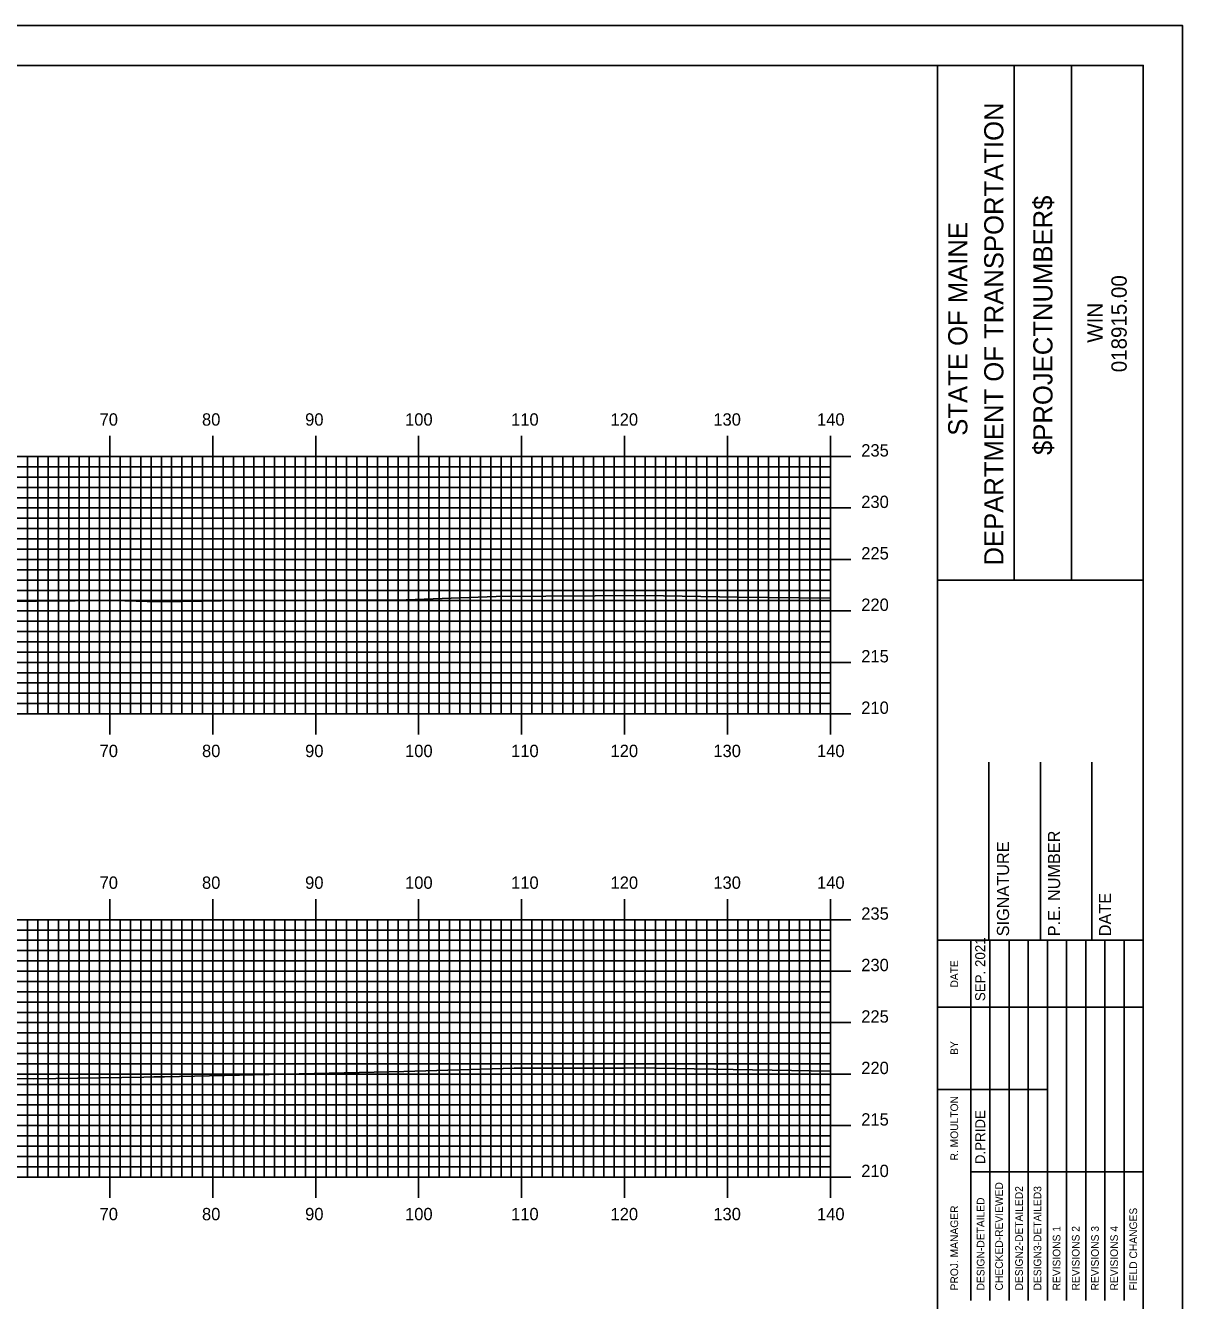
# Model space of a CAD drawing. Extents: x 1804290 to 1804634, y 442591 to 442811.
# Drawn here: x 1804518 to 1804630.4, y 442686.7 to 442810.5 of the extents above; entities that cross this region are included whole.
import ezdxf

# ---------------------------------------------------------------- set-up
doc = ezdxf.new("R2010")
doc.units = 0
for name, color, linetype in [('BORDER', 7, 'Continuous'), ('H_V ANNOTATION', 7, 'Continuous'), ('MAJOR', 7, 'Continuous'), ('MINOR', 7, 'Continuous'), ('PLOT BOUNDARY', 7, 'Continuous'), ('S_Roadway_Centerline', 7, 'Continuous')]:
    doc.layers.add(name, color=color, linetype=linetype)

msp = doc.modelspace()

# ---------------------------------------------------------------- linework, layer by layer
at = {"layer": 'BORDER'}
for p, q in [((1804606.57, 442596.67), (1804606.57, 442806.67)), ((1804614.02, 442756.66), (1804614.02, 442806.66)), ((1804619.61, 442756.66), (1804619.61, 442806.66)), ((1804606.57, 442756.65), (1804626.57, 442756.65)), ((1804611.57, 442721.67), (1804611.57, 442738.97)), ((1804616.57, 442721.67), (1804616.57, 442738.97)), ((1804621.57, 442721.67), (1804621.57, 442738.97)), ((1804606.57, 442721.67), (1804626.57, 442721.67))]:
    msp.add_line(p, q, dxfattribs=at)
msp.add_lwpolyline([(1804306.57, 442596.67), (1804626.57, 442596.67), (1804626.57, 442806.67), (1804306.57, 442806.67)], close=True, dxfattribs=at)
for points in [[(1804609.8, 442715.17), (1804609.8, 442721.67)], [(1804611.66, 442686.68), (1804611.66, 442721.67)], [(1804613.53, 442721.67), (1804613.53, 442686.68)], [(1804615.39, 442686.68), (1804615.39, 442721.67)], [(1804617.25, 442686.68), (1804617.25, 442721.67)], [(1804619.12, 442686.68), (1804619.12, 442721.67)], [(1804620.98, 442686.68), (1804620.98, 442721.67)], [(1804622.84, 442686.68), (1804622.84, 442721.67)], [(1804624.71, 442686.68), (1804624.71, 442721.67)], [(1804609.8, 442686.68), (1804609.8, 442720.26)], [(1804606.57, 442715.17), (1804626.57, 442715.17)], [(1804606.57, 442707.17), (1804609.8, 442707.17)], [(1804609.8, 442707.17), (1804617.25, 442707.17)], [(1804609.8, 442699.17), (1804626.57, 442699.17)]]:
    msp.add_lwpolyline(points, dxfattribs=at)
at = {"layer": 'MAJOR'}
for p, q in [((1804526.17, 442770.67), (1804526.17, 442768.67)), ((1804536.17, 442770.67), (1804536.17, 442768.67)), ((1804546.17, 442770.67), (1804546.17, 442768.67)), ((1804556.17, 442770.67), (1804556.17, 442768.67)), ((1804566.17, 442770.67), (1804566.17, 442768.67)), ((1804576.17, 442770.67), (1804576.17, 442768.67)), ((1804586.17, 442770.67), (1804586.17, 442768.67)), ((1804596.17, 442770.67), (1804596.17, 442768.67)), ((1804316.17, 442768.67), (1804596.17, 442768.67)), ((1804316.17, 442768.67), (1804596.17, 442768.67)), ((1804526.17, 442743.67), (1804526.17, 442768.67)), ((1804536.17, 442743.67), (1804536.17, 442768.67)), ((1804546.17, 442743.67), (1804546.17, 442768.67)), ((1804556.17, 442743.67), (1804556.17, 442768.67)), ((1804566.17, 442743.67), (1804566.17, 442768.67)), ((1804576.17, 442743.67), (1804576.17, 442768.67)), ((1804586.17, 442743.67), (1804586.17, 442768.67)), ((1804598.17, 442768.67), (1804594.16, 442768.67)), ((1804596.17, 442743.67), (1804596.17, 442768.67)), ((1804596.17, 442743.67), (1804596.17, 442768.67)), ((1804316.17, 442763.67), (1804596.17, 442763.67)), ((1804598.17, 442763.67), (1804594.16, 442763.67)), ((1804316.17, 442758.67), (1804596.17, 442758.67)), ((1804598.17, 442758.67), (1804594.16, 442758.67)), ((1804316.17, 442753.67), (1804596.17, 442753.67)), ((1804598.17, 442753.67), (1804594.16, 442753.67)), ((1804316.17, 442748.67), (1804596.17, 442748.67)), ((1804598.17, 442748.67), (1804594.16, 442748.67)), ((1804316.17, 442743.67), (1804596.17, 442743.67)), ((1804316.17, 442743.67), (1804596.17, 442743.67)), ((1804526.17, 442741.66), (1804526.17, 442743.67)), ((1804536.17, 442741.66), (1804536.17, 442743.67)), ((1804546.17, 442741.66), (1804546.17, 442743.67)), ((1804556.17, 442741.66), (1804556.17, 442743.67)), ((1804566.17, 442741.66), (1804566.17, 442743.67)), ((1804576.17, 442741.66), (1804576.17, 442743.67)), ((1804586.17, 442741.66), (1804586.17, 442743.67)), ((1804598.17, 442743.67), (1804594.16, 442743.67)), ((1804596.17, 442741.66), (1804596.17, 442743.67)), ((1804526.17, 442725.67), (1804526.17, 442723.67)), ((1804536.17, 442725.67), (1804536.17, 442723.67)), ((1804546.17, 442725.67), (1804546.17, 442723.67)), ((1804556.17, 442725.67), (1804556.17, 442723.67)), ((1804566.17, 442725.67), (1804566.17, 442723.67)), ((1804576.17, 442725.67), (1804576.17, 442723.67)), ((1804586.17, 442725.67), (1804586.17, 442723.67)), ((1804596.17, 442725.67), (1804596.17, 442723.67)), ((1804316.17, 442723.67), (1804596.17, 442723.67)), ((1804316.17, 442723.67), (1804596.17, 442723.67)), ((1804526.17, 442698.67), (1804526.17, 442723.67)), ((1804536.17, 442698.67), (1804536.17, 442723.67)), ((1804546.17, 442698.67), (1804546.17, 442723.67)), ((1804556.17, 442698.67), (1804556.17, 442723.67)), ((1804566.17, 442698.67), (1804566.17, 442723.67)), ((1804576.17, 442698.67), (1804576.17, 442723.67)), ((1804586.17, 442698.67), (1804586.17, 442723.67)), ((1804598.17, 442723.67), (1804594.16, 442723.67)), ((1804596.17, 442698.67), (1804596.17, 442723.67)), ((1804596.17, 442698.67), (1804596.17, 442723.67)), ((1804316.17, 442718.67), (1804596.17, 442718.67)), ((1804598.17, 442718.67), (1804594.16, 442718.67)), ((1804316.17, 442713.67), (1804596.17, 442713.67)), ((1804598.17, 442713.67), (1804594.16, 442713.67)), ((1804316.17, 442708.67), (1804596.17, 442708.67)), ((1804598.17, 442708.67), (1804594.16, 442708.67)), ((1804316.17, 442703.67), (1804596.17, 442703.67)), ((1804598.17, 442703.67), (1804594.16, 442703.67)), ((1804316.17, 442698.67), (1804596.17, 442698.67)), ((1804316.17, 442698.67), (1804596.17, 442698.67)), ((1804526.17, 442696.66), (1804526.17, 442698.67)), ((1804536.17, 442696.66), (1804536.17, 442698.67)), ((1804546.17, 442696.66), (1804546.17, 442698.67)), ((1804556.17, 442696.66), (1804556.17, 442698.67)), ((1804566.17, 442696.66), (1804566.17, 442698.67)), ((1804576.17, 442696.66), (1804576.17, 442698.67)), ((1804586.17, 442696.66), (1804586.17, 442698.67)), ((1804598.17, 442698.67), (1804594.16, 442698.67)), ((1804596.17, 442696.66), (1804596.17, 442698.67))]:
    msp.add_line(p, q, dxfattribs=at)
at = {"layer": 'MINOR'}
for p, q in [((1804518.17, 442743.67), (1804518.17, 442768.67)), ((1804519.17, 442743.67), (1804519.17, 442768.67)), ((1804520.17, 442743.67), (1804520.17, 442768.67)), ((1804521.17, 442743.67), (1804521.17, 442768.67)), ((1804522.17, 442743.67), (1804522.17, 442768.67)), ((1804523.17, 442743.67), (1804523.17, 442768.67)), ((1804524.17, 442743.67), (1804524.17, 442768.67)), ((1804525.17, 442743.67), (1804525.17, 442768.67)), ((1804527.17, 442743.67), (1804527.17, 442768.67)), ((1804528.17, 442743.67), (1804528.17, 442768.67)), ((1804529.17, 442743.67), (1804529.17, 442768.67)), ((1804530.17, 442743.67), (1804530.17, 442768.67)), ((1804531.17, 442743.67), (1804531.17, 442768.67)), ((1804532.17, 442743.67), (1804532.17, 442768.67)), ((1804533.17, 442743.67), (1804533.17, 442768.67)), ((1804534.17, 442743.67), (1804534.17, 442768.67)), ((1804535.17, 442743.67), (1804535.17, 442768.67)), ((1804537.17, 442743.67), (1804537.17, 442768.67)), ((1804538.17, 442743.67), (1804538.17, 442768.67)), ((1804539.17, 442743.67), (1804539.17, 442768.67)), ((1804540.17, 442743.67), (1804540.17, 442768.67)), ((1804541.17, 442743.67), (1804541.17, 442768.67)), ((1804542.17, 442743.67), (1804542.17, 442768.67)), ((1804543.17, 442743.67), (1804543.17, 442768.67)), ((1804544.17, 442743.67), (1804544.17, 442768.67)), ((1804545.17, 442743.67), (1804545.17, 442768.67)), ((1804547.17, 442743.67), (1804547.17, 442768.67)), ((1804548.17, 442743.67), (1804548.17, 442768.67)), ((1804549.17, 442743.67), (1804549.17, 442768.67)), ((1804550.17, 442743.67), (1804550.17, 442768.67)), ((1804551.17, 442743.67), (1804551.17, 442768.67)), ((1804552.17, 442743.67), (1804552.17, 442768.67)), ((1804553.17, 442743.67), (1804553.17, 442768.67)), ((1804554.17, 442743.67), (1804554.17, 442768.67)), ((1804555.17, 442743.67), (1804555.17, 442768.67)), ((1804557.17, 442743.67), (1804557.17, 442768.67)), ((1804558.17, 442743.67), (1804558.17, 442768.67)), ((1804559.17, 442743.67), (1804559.17, 442768.67)), ((1804560.17, 442743.67), (1804560.17, 442768.67)), ((1804561.17, 442743.67), (1804561.17, 442768.67)), ((1804562.17, 442743.67), (1804562.17, 442768.67)), ((1804563.17, 442743.67), (1804563.17, 442768.67)), ((1804564.17, 442743.67), (1804564.17, 442768.67)), ((1804565.17, 442743.67), (1804565.17, 442768.67)), ((1804567.17, 442743.67), (1804567.17, 442768.67)), ((1804568.17, 442743.67), (1804568.17, 442768.67)), ((1804569.17, 442743.67), (1804569.17, 442768.67)), ((1804570.17, 442743.67), (1804570.17, 442768.67)), ((1804571.17, 442743.67), (1804571.17, 442768.67)), ((1804572.17, 442743.67), (1804572.17, 442768.67)), ((1804573.17, 442743.67), (1804573.17, 442768.67)), ((1804574.17, 442743.67), (1804574.17, 442768.67)), ((1804575.17, 442743.67), (1804575.17, 442768.67)), ((1804577.17, 442743.67), (1804577.17, 442768.67)), ((1804578.17, 442743.67), (1804578.17, 442768.67)), ((1804579.17, 442743.67), (1804579.17, 442768.67)), ((1804580.17, 442743.67), (1804580.17, 442768.67)), ((1804581.17, 442743.67), (1804581.17, 442768.67)), ((1804582.17, 442743.67), (1804582.17, 442768.67)), ((1804583.17, 442743.67), (1804583.17, 442768.67)), ((1804584.17, 442743.67), (1804584.17, 442768.67)), ((1804585.17, 442743.67), (1804585.17, 442768.67)), ((1804587.17, 442743.67), (1804587.17, 442768.67)), ((1804588.17, 442743.67), (1804588.17, 442768.67)), ((1804589.17, 442743.67), (1804589.17, 442768.67)), ((1804590.17, 442743.67), (1804590.17, 442768.67)), ((1804591.17, 442743.67), (1804591.17, 442768.67)), ((1804592.17, 442743.67), (1804592.17, 442768.67)), ((1804593.17, 442743.67), (1804593.17, 442768.67)), ((1804594.17, 442743.67), (1804594.17, 442768.67)), ((1804595.17, 442743.67), (1804595.17, 442768.67)), ((1804316.17, 442767.67), (1804596.17, 442767.67)), ((1804596.17, 442767.67), (1804594.16, 442767.67)), ((1804316.17, 442766.67), (1804596.17, 442766.67)), ((1804596.17, 442766.67), (1804594.16, 442766.67)), ((1804316.17, 442765.67), (1804596.17, 442765.67)), ((1804596.17, 442765.67), (1804594.16, 442765.67)), ((1804316.17, 442764.67), (1804596.17, 442764.67)), ((1804596.17, 442764.67), (1804594.16, 442764.67)), ((1804316.17, 442762.67), (1804596.17, 442762.67)), ((1804596.17, 442762.67), (1804594.16, 442762.67)), ((1804316.17, 442761.67), (1804596.17, 442761.67)), ((1804596.17, 442761.67), (1804594.16, 442761.67)), ((1804316.17, 442760.67), (1804596.17, 442760.67)), ((1804596.17, 442760.67), (1804594.16, 442760.67)), ((1804316.17, 442759.67), (1804596.17, 442759.67)), ((1804596.17, 442759.67), (1804594.16, 442759.67)), ((1804316.17, 442757.67), (1804596.17, 442757.67)), ((1804596.17, 442757.67), (1804594.16, 442757.67)), ((1804316.17, 442756.67), (1804596.17, 442756.67)), ((1804596.17, 442756.67), (1804594.16, 442756.67)), ((1804316.17, 442755.67), (1804596.17, 442755.67)), ((1804596.17, 442755.67), (1804594.16, 442755.67)), ((1804316.17, 442754.67), (1804596.17, 442754.67)), ((1804596.17, 442754.67), (1804594.16, 442754.67)), ((1804316.17, 442752.67), (1804596.17, 442752.67)), ((1804596.17, 442752.67), (1804594.16, 442752.67)), ((1804316.17, 442751.67), (1804596.17, 442751.67)), ((1804596.17, 442751.67), (1804594.16, 442751.67)), ((1804316.17, 442750.67), (1804596.17, 442750.67)), ((1804596.17, 442750.67), (1804594.16, 442750.67)), ((1804316.17, 442749.67), (1804596.17, 442749.67)), ((1804596.17, 442749.67), (1804594.16, 442749.67)), ((1804316.17, 442747.67), (1804596.17, 442747.67)), ((1804596.17, 442747.67), (1804594.16, 442747.67)), ((1804316.17, 442746.67), (1804596.17, 442746.67)), ((1804596.17, 442746.67), (1804594.16, 442746.67)), ((1804316.17, 442745.67), (1804596.17, 442745.67)), ((1804596.17, 442745.67), (1804594.16, 442745.67)), ((1804316.17, 442744.67), (1804596.17, 442744.67)), ((1804596.17, 442744.67), (1804594.16, 442744.67)), ((1804518.17, 442698.67), (1804518.17, 442723.67)), ((1804519.17, 442698.67), (1804519.17, 442723.67)), ((1804520.17, 442698.67), (1804520.17, 442723.67)), ((1804521.17, 442698.67), (1804521.17, 442723.67)), ((1804522.17, 442698.67), (1804522.17, 442723.67)), ((1804523.17, 442698.67), (1804523.17, 442723.67)), ((1804524.17, 442698.67), (1804524.17, 442723.67)), ((1804525.17, 442698.67), (1804525.17, 442723.67)), ((1804527.17, 442698.67), (1804527.17, 442723.67)), ((1804528.17, 442698.67), (1804528.17, 442723.67)), ((1804529.17, 442698.67), (1804529.17, 442723.67)), ((1804530.17, 442698.67), (1804530.17, 442723.67)), ((1804531.17, 442698.67), (1804531.17, 442723.67)), ((1804532.17, 442698.67), (1804532.17, 442723.67)), ((1804533.17, 442698.67), (1804533.17, 442723.67)), ((1804534.17, 442698.67), (1804534.17, 442723.67)), ((1804535.17, 442698.67), (1804535.17, 442723.67)), ((1804537.17, 442698.67), (1804537.17, 442723.67)), ((1804538.17, 442698.67), (1804538.17, 442723.67)), ((1804539.17, 442698.67), (1804539.17, 442723.67)), ((1804540.17, 442698.67), (1804540.17, 442723.67)), ((1804541.17, 442698.67), (1804541.17, 442723.67)), ((1804542.17, 442698.67), (1804542.17, 442723.67)), ((1804543.17, 442698.67), (1804543.17, 442723.67)), ((1804544.17, 442698.67), (1804544.17, 442723.67)), ((1804545.17, 442698.67), (1804545.17, 442723.67)), ((1804547.17, 442698.67), (1804547.17, 442723.67)), ((1804548.17, 442698.67), (1804548.17, 442723.67)), ((1804549.17, 442698.67), (1804549.17, 442723.67)), ((1804550.17, 442698.67), (1804550.17, 442723.67)), ((1804551.17, 442698.67), (1804551.17, 442723.67)), ((1804552.17, 442698.67), (1804552.17, 442723.67)), ((1804553.17, 442698.67), (1804553.17, 442723.67)), ((1804554.17, 442698.67), (1804554.17, 442723.67)), ((1804555.17, 442698.67), (1804555.17, 442723.67)), ((1804557.17, 442698.67), (1804557.17, 442723.67)), ((1804558.17, 442698.67), (1804558.17, 442723.67)), ((1804559.17, 442698.67), (1804559.17, 442723.67)), ((1804560.17, 442698.67), (1804560.17, 442723.67)), ((1804561.17, 442698.67), (1804561.17, 442723.67)), ((1804562.17, 442698.67), (1804562.17, 442723.67)), ((1804563.17, 442698.67), (1804563.17, 442723.67)), ((1804564.17, 442698.67), (1804564.17, 442723.67)), ((1804565.17, 442698.67), (1804565.17, 442723.67)), ((1804567.17, 442698.67), (1804567.17, 442723.67)), ((1804568.17, 442698.67), (1804568.17, 442723.67)), ((1804569.17, 442698.67), (1804569.17, 442723.67)), ((1804570.17, 442698.67), (1804570.17, 442723.67)), ((1804571.17, 442698.67), (1804571.17, 442723.67)), ((1804572.17, 442698.67), (1804572.17, 442723.67)), ((1804573.17, 442698.67), (1804573.17, 442723.67)), ((1804574.17, 442698.67), (1804574.17, 442723.67)), ((1804575.17, 442698.67), (1804575.17, 442723.67)), ((1804577.17, 442698.67), (1804577.17, 442723.67)), ((1804578.17, 442698.67), (1804578.17, 442723.67)), ((1804579.17, 442698.67), (1804579.17, 442723.67)), ((1804580.17, 442698.67), (1804580.17, 442723.67)), ((1804581.17, 442698.67), (1804581.17, 442723.67)), ((1804582.17, 442698.67), (1804582.17, 442723.67)), ((1804583.17, 442698.67), (1804583.17, 442723.67)), ((1804584.17, 442698.67), (1804584.17, 442723.67)), ((1804585.17, 442698.67), (1804585.17, 442723.67)), ((1804587.17, 442698.67), (1804587.17, 442723.67)), ((1804588.17, 442698.67), (1804588.17, 442723.67)), ((1804589.17, 442698.67), (1804589.17, 442723.67)), ((1804590.17, 442698.67), (1804590.17, 442723.67)), ((1804591.17, 442698.67), (1804591.17, 442723.67)), ((1804592.17, 442698.67), (1804592.17, 442723.67)), ((1804593.17, 442698.67), (1804593.17, 442723.67)), ((1804594.17, 442698.67), (1804594.17, 442723.67)), ((1804595.17, 442698.67), (1804595.17, 442723.67)), ((1804316.17, 442722.67), (1804596.17, 442722.67)), ((1804316.17, 442721.67), (1804596.17, 442721.67)), ((1804596.17, 442722.67), (1804594.16, 442722.67)), ((1804596.17, 442721.67), (1804594.16, 442721.67)), ((1804316.17, 442720.67), (1804596.17, 442720.67)), ((1804596.17, 442720.67), (1804594.16, 442720.67)), ((1804316.17, 442719.67), (1804596.17, 442719.67)), ((1804596.17, 442719.67), (1804594.16, 442719.67)), ((1804316.17, 442717.67), (1804596.17, 442717.67)), ((1804316.17, 442716.67), (1804596.17, 442716.67)), ((1804596.17, 442717.67), (1804594.16, 442717.67)), ((1804596.17, 442716.67), (1804594.16, 442716.67)), ((1804316.17, 442715.67), (1804596.17, 442715.67)), ((1804596.17, 442715.67), (1804594.16, 442715.67)), ((1804316.17, 442714.67), (1804596.17, 442714.67)), ((1804596.17, 442714.67), (1804594.16, 442714.67)), ((1804316.17, 442712.67), (1804596.17, 442712.67)), ((1804316.17, 442711.67), (1804596.17, 442711.67)), ((1804596.17, 442712.67), (1804594.16, 442712.67)), ((1804596.17, 442711.67), (1804594.16, 442711.67)), ((1804316.17, 442710.67), (1804596.17, 442710.67)), ((1804596.17, 442710.67), (1804594.16, 442710.67)), ((1804316.17, 442709.67), (1804596.17, 442709.67)), ((1804596.17, 442709.67), (1804594.16, 442709.67)), ((1804316.17, 442707.67), (1804596.17, 442707.67)), ((1804316.17, 442706.67), (1804596.17, 442706.67)), ((1804596.17, 442707.67), (1804594.16, 442707.67)), ((1804596.17, 442706.67), (1804594.16, 442706.67)), ((1804316.17, 442705.67), (1804596.17, 442705.67)), ((1804596.17, 442705.67), (1804594.16, 442705.67)), ((1804316.17, 442704.67), (1804596.17, 442704.67)), ((1804596.17, 442704.67), (1804594.16, 442704.67)), ((1804316.17, 442702.67), (1804596.17, 442702.67)), ((1804316.17, 442701.67), (1804596.17, 442701.67)), ((1804596.17, 442702.67), (1804594.16, 442702.67)), ((1804596.17, 442701.67), (1804594.16, 442701.67)), ((1804316.17, 442700.67), (1804596.17, 442700.67)), ((1804596.17, 442700.67), (1804594.16, 442700.67)), ((1804316.17, 442699.67), (1804596.17, 442699.67)), ((1804596.17, 442699.67), (1804594.16, 442699.67))]:
    msp.add_line(p, q, dxfattribs=at)
at = {"layer": 'PLOT BOUNDARY'}
msp.add_lwpolyline([(1804290.38, 442590.55), (1804630.38, 442590.55), (1804630.38, 442810.55), (1804290.38, 442810.55)], close=True, dxfattribs=at)
at = {"layer": 'S_Roadway_Centerline'}
for points in [[(1804511.52, 442754.56), (1804526.57, 442754.69), (1804529.79, 442754.59), (1804533.18, 442754.58), (1804538.84, 442754.67), (1804554.94, 442754.75), (1804563.7, 442755.06), (1804578.14, 442755.18), (1804587.22, 442755.01), (1804596.17, 442754.91)], [(1804507.56, 442708.31), (1804518.78, 442708.2), (1804529.48, 442708.36), (1804530.43, 442708.39), (1804531.48, 442708.39), (1804551.85, 442708.85), (1804554.74, 442708.92), (1804565.46, 442709.24), (1804576.15, 442709.26), (1804577.27, 442709.29), (1804596.17, 442708.95)]]:
    msp.add_lwpolyline(points, dxfattribs=at)

# ---------------------------------------------------------------- texts
at = {"layer": 'BORDER'}
for s, height, p in [('DEPARTMENT OF TRANSPORTATION', 1.8635, (1804612.98, 442758.08)), ('$PROJECTNUMBER$', 1.8635, (1804617.75, 442768.82)), ('STATE OF MAINE', 1.8635, (1804609.48, 442770.69)), ('018915.00', 1.491, (1804624.96, 442776.86)), ('WIN', 1.491, (1804622.64, 442779.73)), ('P.E. NUMBER', 1.1811, (1804618.49, 442722.06)), ('SIGNATURE', 1.181, (1804613.53, 442722.06)), ('DATE', 1.181, (1804623.45, 442722.06)), ('SEP. 2021', 0.969, (1804611.21, 442715.76)), ('DATE', 0.743, (1804608.58, 442717.08)), ('BY', 0.743, (1804608.58, 442710.54)), ('R. MOULTON', 0.745, (1804608.58, 442700.28)), ('D.PRIDE', 0.969, (1804611.21, 442699.92)), ('CHECKED-REVIEWED', 0.7455, (1804612.93, 442687.65)), ('DESIGN2-DETAILED2', 0.7455, (1804614.87, 442687.65)), ('DESIGN3-DETAILED3', 0.7455, (1804616.66, 442687.65)), ('PROJ. MANAGER', 0.7455, (1804608.58, 442687.65)), ('DESIGN-DETAILED', 0.7455, (1804611.14, 442687.65)), ('FIELD CHANGES', 0.7455, (1804625.97, 442687.65)), ('REVISIONS 1', 0.7455, (1804618.52, 442687.65)), ('REVISIONS 2', 0.7455, (1804620.38, 442687.65)), ('REVISIONS 3', 0.7455, (1804622.25, 442687.65)), ('REVISIONS 4', 0.7455, (1804624.11, 442687.65))]:
    msp.add_text(s, height=height, rotation=90, dxfattribs=at).set_placement(p)
at = {"layer": 'H_V ANNOTATION'}
for s, p in [('70', (1804525.17, 442771.67)), ('80', (1804535.12, 442771.67)), ('90', (1804545.14, 442771.67)), ('100', (1804554.85, 442771.67)), ('110', (1804565.15, 442771.67)), ('120', (1804574.81, 442771.67)), ('130', (1804584.8, 442771.67)), ('140', (1804594.87, 442771.67)), ('235', (1804599.17, 442768.67)), ('230', (1804599.17, 442763.67)), ('225', (1804599.17, 442758.67)), ('220', (1804599.17, 442753.67)), ('215', (1804599.17, 442748.67)), ('210', (1804599.17, 442743.67)), ('70', (1804525.17, 442739.47)), ('80', (1804535.12, 442739.47)), ('90', (1804545.14, 442739.47)), ('100', (1804554.85, 442739.47)), ('110', (1804565.15, 442739.47)), ('120', (1804574.81, 442739.47)), ('130', (1804584.8, 442739.47)), ('140', (1804594.87, 442739.47)), ('70', (1804525.17, 442726.67)), ('80', (1804535.12, 442726.67)), ('90', (1804545.14, 442726.67)), ('100', (1804554.85, 442726.67)), ('110', (1804565.15, 442726.67)), ('120', (1804574.81, 442726.67)), ('130', (1804584.8, 442726.67)), ('140', (1804594.87, 442726.67)), ('235', (1804599.17, 442723.67)), ('230', (1804599.17, 442718.67)), ('225', (1804599.17, 442713.67)), ('220', (1804599.17, 442708.67)), ('215', (1804599.17, 442703.67)), ('210', (1804599.17, 442698.67)), ('70', (1804525.17, 442694.47)), ('80', (1804535.12, 442694.47)), ('90', (1804545.14, 442694.47)), ('100', (1804554.85, 442694.47)), ('110', (1804565.15, 442694.47)), ('120', (1804574.81, 442694.47)), ('130', (1804584.8, 442694.47)), ('140', (1804594.87, 442694.47))]:
    msp.add_text(s, height=1.2, dxfattribs=at).set_placement(p)

doc.saveas('drawing.dxf')
